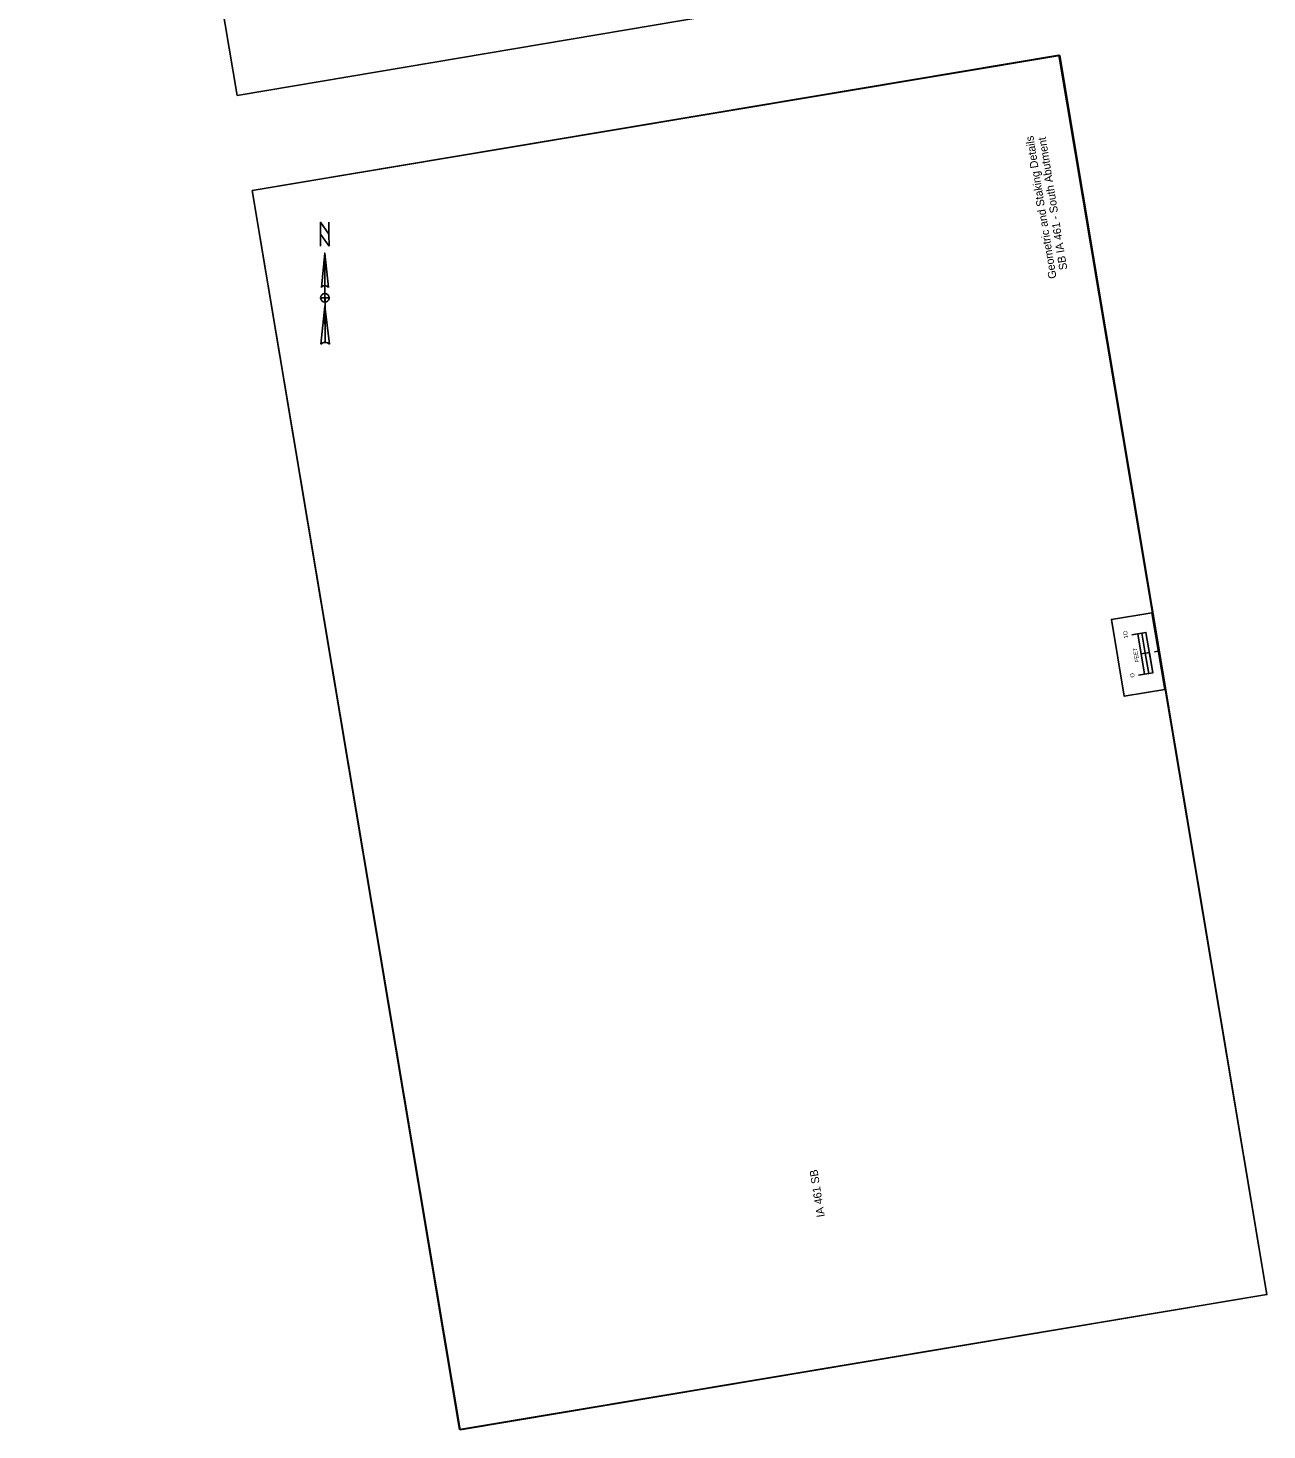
# Model space of a CAD drawing. Extents: x 21487943 to 21488253, y 8075016 to 8075692.
# Drawn here: x 21487943.4 to 21488252.9, y 8075015.7 to 8075365.9 of the extents above; entities that cross this region are included whole.
import ezdxf

# ---------------------------------------------------------------- set-up
doc = ezdxf.new("R2010")
doc.units = 0
for name, color, linetype in [('Default', 7, 'Continuous'), ('dsnCellElements', 7, 'Continuous'), ('dsnCellsScaleBlock', 7, 'Continuous'), ('dsnTextRoadwayLabel', 7, 'Continuous'), ('Level 20', 7, 'Continuous'), ('NamedBoundary', 7, 'Continuous')]:
    doc.layers.add(name, color=color, linetype=linetype)

msp = doc.modelspace()

# ---------------------------------------------------------------- linework, layer by layer
at = {"layer": 'Default'}
for p in [(21488225.75, 8075210.25), (21488225.75, 8075210.25), (21488224.81, 8075210.09)]:
    msp.add_line(p, (21488224.81, 8075210.09), dxfattribs=at)
at = {"layer": 'dsnCellElements'}
for p, q in [((21488017.51, 8075309.69), (21488018.41, 8075301.11)), ((21488017.51, 8075309.69), (21488017.61, 8075287.38)), ((21488016.69, 8075301.11), (21488016.69, 8075301.11)), ((21488016.72, 8075301.18), (21488016.88, 8075301.36)), ((21488016.54, 8075286.95), (21488017.57, 8075296.39)), ((21488017.56, 8075297.46), (21488017.56, 8075297.46))]:
    msp.add_line(p, q, dxfattribs=at)
for points in [[(21488016.43, 8075311.4), (21488016.41, 8075317.41), (21488018.56, 8075314.41), (21488018.55, 8075317.42)], [(21488016.69, 8075301.11), (21488017.51, 8075309.69), (21488017.55, 8075301.54)], [(21488018.63, 8075298.54), (21488017.56, 8075298.53), (21488017.55, 8075299.61)], [(21488017.56, 8075297.46), (21488017.56, 8075298.53), (21488016.49, 8075298.53)], [(21488017.61, 8075287.38), (21488017.57, 8075296.39), (21488018.68, 8075286.95)]]:
    msp.add_lwpolyline(points, dxfattribs=at)
for points in [[(21488018.58, 8075311.41), (21488016.42, 8075314.4), (21488016.41, 8075317.41), (21488018.56, 8075314.41)], [(21488217.26, 8075198.95), (21488214.03, 8075218.15), (21488224.14, 8075219.85), (21488227.36, 8075200.64)]]:
    msp.add_lwpolyline(points, close=True, dxfattribs=at)
for centre, radius, start, end in [((21488017.56, 8075298.53), 1.07, 90.2458, 180.2458), ((21488017.55, 8075300.47), 1.07, 90.2662, 143.3715), ((21488017.55, 8075300.47), 1.07, 37.0938, 90.2676), ((21488017.56, 8075298.53), 1.07, 0.2458, 90.2458), ((21488017.56, 8075298.53), 1.07, 180.2458, 270.2458), ((21488017.56, 8075298.53), 1.07, 270.2458, 0.2458), ((21488017.61, 8075285.83), 1.55, 90.2352, 133.8647), ((21488017.61, 8075285.82), 1.56, 46.6478, 90.2464)]:
    msp.add_arc(centre, radius, start, end, dxfattribs=at)
at = {"layer": 'dsnCellsScaleBlock'}
msp.add_line((21488223.53, 8075209.87), (21488221.51, 8075209.53), dxfattribs=at)
msp.add_line((21488223.53, 8075209.87), (21488221.51, 8075209.53), dxfattribs=at)
for points in [[(21488227.36, 8075200.64), (21488217.26, 8075198.95), (21488214.03, 8075218.15), (21488224.14, 8075219.85)], [(21488222.51, 8075209.7), (21488221.66, 8075214.76), (21488220.66, 8075214.59), (21488221.51, 8075209.53)], [(21488224.38, 8075204.82), (21488223.53, 8075209.87), (21488222.51, 8075209.7), (21488223.36, 8075204.65)]]:
    msp.add_lwpolyline(points, close=True, dxfattribs=at)
for points in [[(21488220.84, 8075204.23), (21488224.38, 8075204.82), (21488222.68, 8075214.93), (21488219.14, 8075214.33)], [(21488222.35, 8075204.48), (21488220.66, 8075214.59)]]:
    msp.add_lwpolyline(points, dxfattribs=at)
at = {"layer": 'NamedBoundary'}
for points in [[(21487995.59, 8075349.08), (21488196.57, 8075383.03), (21488144.36, 8075692.1), (21487943.38, 8075658.16)], [(21488051.37, 8075015.65), (21488252.91, 8075049.48), (21488200.93, 8075359.16), (21487999.39, 8075325.33)], [(21488051.14, 8075015.75), (21488252.91, 8075049.48), (21488201.15, 8075359.06), (21487999.39, 8075325.33)]]:
    msp.add_lwpolyline(points, close=True, dxfattribs=at)

# ---------------------------------------------------------------- texts
at = {"layer": 'dsnCellsScaleBlock'}
for s, height, p in [('1O', 1.025, (21488218.24, 8075213.51)), ('FEET', 1.025, (21488221, 8075207.58)), ('O', 1.02, (21488219.88, 8075203.73))]:
    msp.add_text(s, height=height, rotation=99.5277, dxfattribs=at).set_placement(p)
at = {"layer": 'dsnTextRoadwayLabel'}
msp.add_text('IA 461 SB', height=2, rotation=98.9826, dxfattribs=at).set_placement((21488142.46, 8075068.96))
at = {"layer": 'Level 20'}
for s, p in [('Geometric and Staking Details', (21488200.35, 8075303.46)), ('SB IA 461 - South Abutment', (21488203.04, 8075305.63))]:
    msp.add_text(s, height=2, rotation=99.2873, dxfattribs=at).set_placement(p)

doc.saveas('drawing.dxf')
